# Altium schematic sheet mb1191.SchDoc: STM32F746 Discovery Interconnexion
size A4; Date: 25-FEB-2015; Author: A.B; CompanyName: STMicroelectronics; Address1: 12, Rue Jules HOROWITZ; Address2: 38019 Grenoble; Address3: FRANCE; DocumentNumber: MB1191; Revision: B-02; SheetNumber: 1; SheetTotal: 13; Project: STM32F746G-DISCO
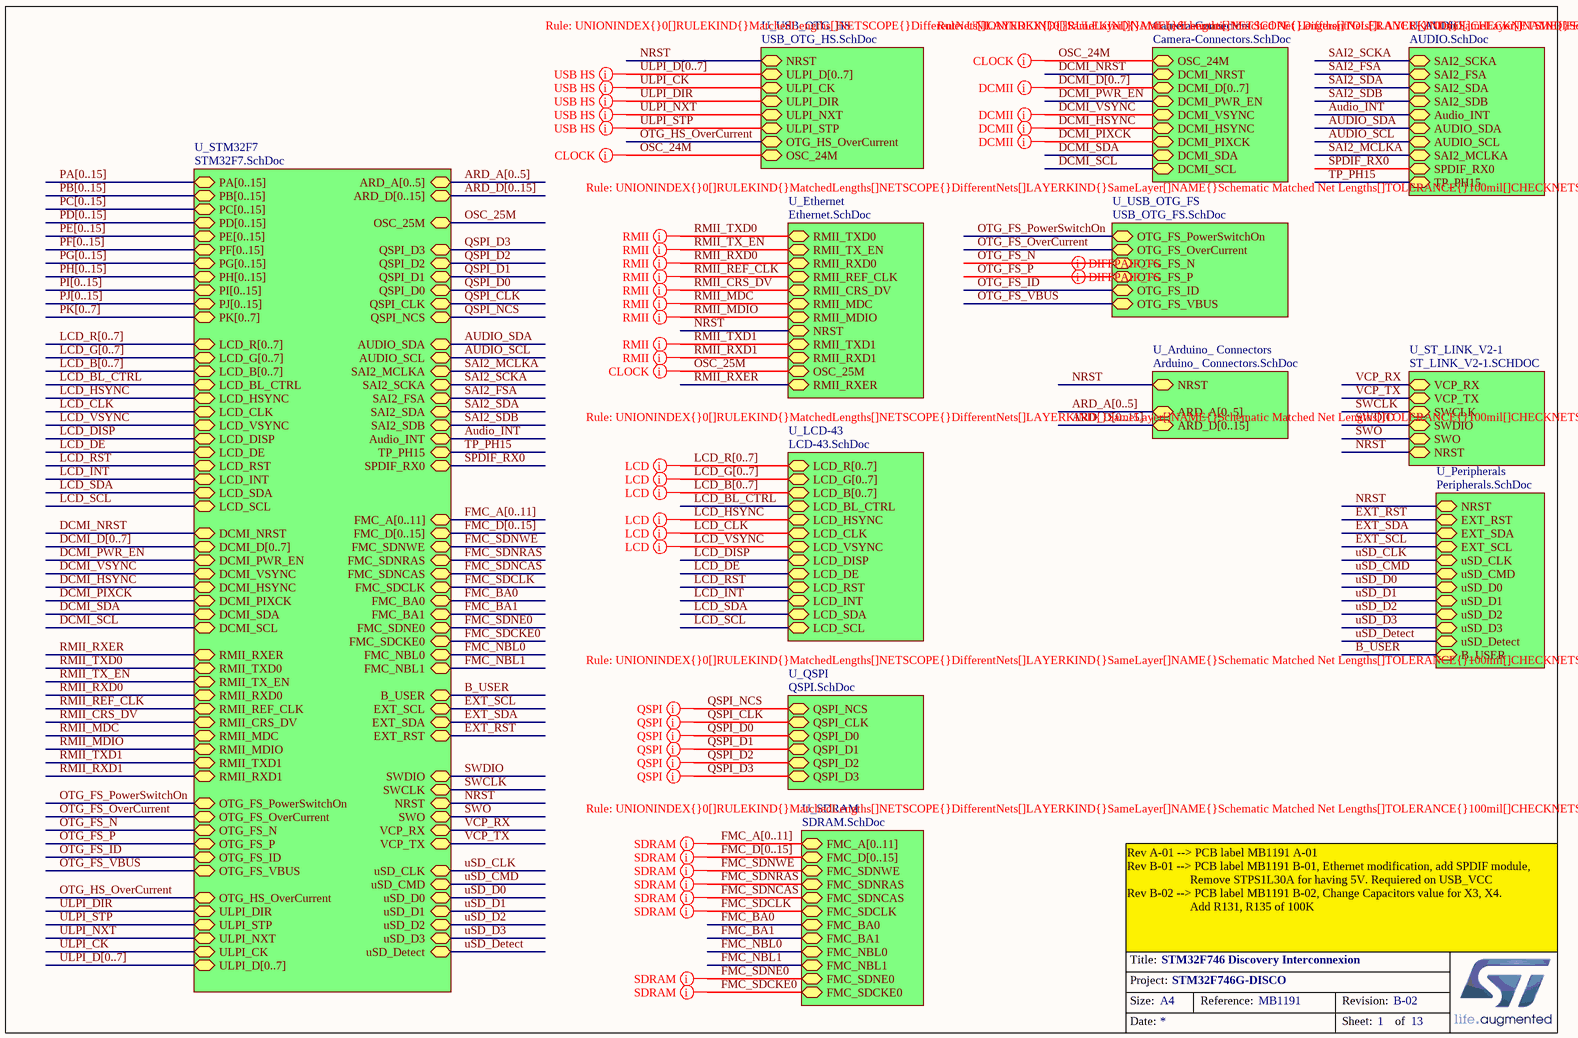
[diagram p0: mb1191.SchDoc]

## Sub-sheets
Camera-Connectors = Camera-Connectors.SchDoc: OSC_24M, DCMI_NRST, DCMI_D[0..7], DCMI_PWR_EN, DCMI_VSYNC, DCMI_HSYNC, DCMI_PIXCK, DCMI_SDA, DCMI_SCL
U_Arduino_ Connectors = Arduino_ Connectors.SchDoc: NRST, ARD_A[0..5], ARD_D[0..15]
U_AUDIO = AUDIO.SchDoc: AUDIO_SDA, AUDIO_SCL, SAI2_MCLKA, SPDIF_RX0, TP_PH15, SAI2_SCKA, SAI2_FSA, SAI2_SDA, SAI2_SDB, Audio_INT
U_Ethernet = Ethernet.SchDoc: RMII_TXD0, RMII_TX_EN, RMII_RXD0, RMII_REF_CLK, RMII_CRS_DV, RMII_MDC, RMII_MDIO, NRST, RMII_TXD1, RMII_RXD1, OSC_25M, RMII_RXER
U_LCD-43 = LCD-43.SchDoc: LCD_R[0..7], LCD_BL_CTRL, LCD_B[0..7], LCD_G[0..7], LCD_HSYNC, LCD_CLK, LCD_VSYNC, LCD_DISP, LCD_DE, LCD_RST, LCD_INT, LCD_SDA, LCD_SCL
U_Peripherals = Peripherals.SchDoc: NRST, EXT_RST, EXT_SCL, EXT_SDA, uSD_CLK, uSD_CMD, uSD_D0, uSD_D1, uSD_D2, uSD_D3, uSD_Detect, B_USER
U_QSPI = QSPI.SchDoc: QSPI_D0, QSPI_D3, QSPI_D1, QSPI_CLK, QSPI_NCS, QSPI_D2
U_SDRAM = SDRAM.SchDoc: FMC_A[0..11], FMC_D[0..15], FMC_SDNWE, FMC_SDNRAS, FMC_SDNCAS, FMC_SDCLK, FMC_BA0, FMC_BA1, FMC_NBL0, FMC_NBL1, FMC_SDNE0, FMC_SDCKE0
U_ST_LINK_V2-1 = ST_LINK_V2-1.SCHDOC: SWDIO, SWCLK, NRST, VCP_RX, VCP_TX, SWO
U_STM32F7 = STM32F7.SchDoc: PA[0..15], PB[0..15], PC[0..15], PD[0..15], PE[0..15], PF[0..15], PG[0..15], PH[0..15], PI[0..15], PJ[0..15], PK[0..7], OSC_25M, LCD_R[0..7], LCD_BL_CTRL, LCD_B[0..7], LCD_G[0..7], LCD_HSYNC, LCD_CLK, LCD_VSYNC, LCD_DISP, LCD_DE, LCD_RST, LCD_INT, LCD_SDA, LCD_SCL, DCMI_NRST, DCMI_D[0..7], DCMI_PWR_EN, DCMI_VSYNC, DCMI_HSYNC, DCMI_PIXCK, DCMI_SDA, DCMI_SCL, RMII_TXD0, RMII_TX_EN, RMII_RXD0, RMII_REF_CLK, RMII_CRS_DV, RMII_MDC, RMII_MDIO, RMII_TXD1, RMII_RXD1, ULPI_D[0..7], ULPI_CK, ULPI_DIR, ULPI_NXT, ULPI_STP, OTG_FS_N, OTG_FS_P, OTG_FS_ID, OTG_FS_VBUS, OTG_FS_PowerSwitchOn, OTG_FS_OverCurrent, QSPI_D0, QSPI_D3, QSPI_D1, QSPI_CLK, QSPI_NCS, AUDIO_SDA, AUDIO_SCL, SAI2_MCLKA, EXT_SCL, EXT_SDA, EXT_RST, uSD_CLK, uSD_CMD, uSD_D0, uSD_D1, uSD_D2, uSD_D3, uSD_Detect, SWDIO, SWCLK, NRST, SWO, VCP_RX, VCP_TX, FMC_A[0..11], FMC_D[0..15], FMC_SDNWE, FMC_SDNRAS, FMC_SDNCAS, FMC_SDCLK, FMC_BA0, FMC_BA1, FMC_SDNE0, FMC_SDCKE0, FMC_NBL0, FMC_NBL1, SPDIF_RX0, QSPI_D2, B_USER, ARD_A[0..5], ARD_D[0..15], RMII_RXER, OTG_HS_OverCurrent, SAI2_SCKA, SAI2_FSA, SAI2_SDA, SAI2_SDB, Audio_INT, TP_PH15
U_USB_OTG_FS = USB_OTG_FS.SchDoc: OTG_FS_PowerSwitchOn, OTG_FS_OverCurrent, OTG_FS_N, OTG_FS_P, OTG_FS_ID, OTG_FS_VBUS
U_USB_OTG_HS = USB_OTG_HS.SchDoc: ULPI_D[0..7], ULPI_CK, ULPI_DIR, ULPI_NXT, ULPI_STP, OSC_24M, NRST, OTG_HS_OverCurrent

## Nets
Audio_INT: sheet U_AUDIO/Audio_INT, sheet U_STM32F7/Audio_INT
AUDIO_SCL: sheet U_AUDIO/AUDIO_SCL, sheet U_STM32F7/AUDIO_SCL
AUDIO_SDA: sheet U_AUDIO/AUDIO_SDA, sheet U_STM32F7/AUDIO_SDA
B_USER: sheet U_Peripherals/B_USER, sheet U_STM32F7/B_USER
DCMI_HSYNC: sheet U_STM32F7/DCMI_HSYNC, sheet Camera-Connectors/DCMI_HSYNC
DCMI_NRST: sheet U_STM32F7/DCMI_NRST, sheet Camera-Connectors/DCMI_NRST
DCMI_PIXCK: sheet U_STM32F7/DCMI_PIXCK, sheet Camera-Connectors/DCMI_PIXCK
DCMI_PWR_EN: sheet U_STM32F7/DCMI_PWR_EN, sheet Camera-Connectors/DCMI_PWR_EN
DCMI_SCL: sheet U_STM32F7/DCMI_SCL, sheet Camera-Connectors/DCMI_SCL
DCMI_SDA: sheet U_STM32F7/DCMI_SDA, sheet Camera-Connectors/DCMI_SDA
DCMI_VSYNC: sheet U_STM32F7/DCMI_VSYNC, sheet Camera-Connectors/DCMI_VSYNC
EXT_RST: sheet U_Peripherals/EXT_RST, sheet U_STM32F7/EXT_RST
EXT_SCL: sheet U_Peripherals/EXT_SCL, sheet U_STM32F7/EXT_SCL
EXT_SDA: sheet U_Peripherals/EXT_SDA, sheet U_STM32F7/EXT_SDA
FMC_BA0: sheet U_SDRAM/FMC_BA0, sheet U_STM32F7/FMC_BA0
FMC_BA1: sheet U_SDRAM/FMC_BA1, sheet U_STM32F7/FMC_BA1
FMC_NBL0: sheet U_SDRAM/FMC_NBL0, sheet U_STM32F7/FMC_NBL0
FMC_NBL1: sheet U_SDRAM/FMC_NBL1, sheet U_STM32F7/FMC_NBL1
FMC_SDCKE0: sheet U_SDRAM/FMC_SDCKE0, sheet U_STM32F7/FMC_SDCKE0
FMC_SDCLK: sheet U_SDRAM/FMC_SDCLK, sheet U_STM32F7/FMC_SDCLK
FMC_SDNCAS: sheet U_SDRAM/FMC_SDNCAS, sheet U_STM32F7/FMC_SDNCAS
FMC_SDNE0: sheet U_SDRAM/FMC_SDNE0, sheet U_STM32F7/FMC_SDNE0
FMC_SDNRAS: sheet U_SDRAM/FMC_SDNRAS, sheet U_STM32F7/FMC_SDNRAS
FMC_SDNWE: sheet U_SDRAM/FMC_SDNWE, sheet U_STM32F7/FMC_SDNWE
LCD_BL_CTRL: sheet U_LCD-43/LCD_BL_CTRL, sheet U_STM32F7/LCD_BL_CTRL
LCD_CLK: sheet U_LCD-43/LCD_CLK, sheet U_STM32F7/LCD_CLK
LCD_DE: sheet U_LCD-43/LCD_DE, sheet U_STM32F7/LCD_DE
LCD_DISP: sheet U_LCD-43/LCD_DISP, sheet U_STM32F7/LCD_DISP
LCD_HSYNC: sheet U_LCD-43/LCD_HSYNC, sheet U_STM32F7/LCD_HSYNC
LCD_INT: sheet U_LCD-43/LCD_INT, sheet U_STM32F7/LCD_INT
LCD_RST: sheet U_LCD-43/LCD_RST, sheet U_STM32F7/LCD_RST
LCD_SCL: sheet U_LCD-43/LCD_SCL, sheet U_STM32F7/LCD_SCL
LCD_SDA: sheet U_LCD-43/LCD_SDA, sheet U_STM32F7/LCD_SDA
LCD_VSYNC: sheet U_LCD-43/LCD_VSYNC, sheet U_STM32F7/LCD_VSYNC
NRST: sheet U_ST_LINK_V2-1/NRST, sheet U_Peripherals/NRST, sheet U_Arduino_ Connectors/NRST, sheet U_USB_OTG_HS/NRST, sheet U_STM32F7/NRST, sheet U_Ethernet/NRST
OSC_24M: sheet U_USB_OTG_HS/OSC_24M, sheet Camera-Connectors/OSC_24M
OSC_25M: sheet U_STM32F7/OSC_25M, sheet U_Ethernet/OSC_25M
OTG_FS_ID: sheet U_USB_OTG_FS/OTG_FS_ID, sheet U_STM32F7/OTG_FS_ID
OTG_FS_N: sheet U_USB_OTG_FS/OTG_FS_N, sheet U_STM32F7/OTG_FS_N
OTG_FS_OverCurrent: sheet U_USB_OTG_FS/OTG_FS_OverCurrent, sheet U_STM32F7/OTG_FS_OverCurrent
OTG_FS_P: sheet U_USB_OTG_FS/OTG_FS_P, sheet U_STM32F7/OTG_FS_P
OTG_FS_PowerSwitchOn: sheet U_USB_OTG_FS/OTG_FS_PowerSwitchOn, sheet U_STM32F7/OTG_FS_PowerSwitchOn
OTG_FS_VBUS: sheet U_USB_OTG_FS/OTG_FS_VBUS, sheet U_STM32F7/OTG_FS_VBUS
OTG_HS_OverCurrent: sheet U_USB_OTG_HS/OTG_HS_OverCurrent, sheet U_STM32F7/OTG_HS_OverCurrent
QSPI_CLK: sheet U_QSPI/QSPI_CLK, sheet U_STM32F7/QSPI_CLK
QSPI_D0: sheet U_QSPI/QSPI_D0, sheet U_STM32F7/QSPI_D0
QSPI_D1: sheet U_QSPI/QSPI_D1, sheet U_STM32F7/QSPI_D1
QSPI_D2: sheet U_QSPI/QSPI_D2, sheet U_STM32F7/QSPI_D2
QSPI_D3: sheet U_QSPI/QSPI_D3, sheet U_STM32F7/QSPI_D3
QSPI_NCS: sheet U_QSPI/QSPI_NCS, sheet U_STM32F7/QSPI_NCS
RMII_CRS_DV: sheet U_STM32F7/RMII_CRS_DV, sheet U_Ethernet/RMII_CRS_DV
RMII_MDC: sheet U_STM32F7/RMII_MDC, sheet U_Ethernet/RMII_MDC
RMII_MDIO: sheet U_STM32F7/RMII_MDIO, sheet U_Ethernet/RMII_MDIO
RMII_REF_CLK: sheet U_STM32F7/RMII_REF_CLK, sheet U_Ethernet/RMII_REF_CLK
RMII_RXD0: sheet U_STM32F7/RMII_RXD0, sheet U_Ethernet/RMII_RXD0
RMII_RXD1: sheet U_STM32F7/RMII_RXD1, sheet U_Ethernet/RMII_RXD1
RMII_RXER: sheet U_STM32F7/RMII_RXER, sheet U_Ethernet/RMII_RXER
RMII_TX_EN: sheet U_STM32F7/RMII_TX_EN, sheet U_Ethernet/RMII_TX_EN
RMII_TXD0: sheet U_STM32F7/RMII_TXD0, sheet U_Ethernet/RMII_TXD0
RMII_TXD1: sheet U_STM32F7/RMII_TXD1, sheet U_Ethernet/RMII_TXD1
SAI2_FSA: sheet U_AUDIO/SAI2_FSA, sheet U_STM32F7/SAI2_FSA
SAI2_MCLKA: sheet U_AUDIO/SAI2_MCLKA, sheet U_STM32F7/SAI2_MCLKA
SAI2_SCKA: sheet U_AUDIO/SAI2_SCKA, sheet U_STM32F7/SAI2_SCKA
SAI2_SDA: sheet U_AUDIO/SAI2_SDA, sheet U_STM32F7/SAI2_SDA
SAI2_SDB: sheet U_AUDIO/SAI2_SDB, sheet U_STM32F7/SAI2_SDB
SPDIF_RX0: sheet U_AUDIO/SPDIF_RX0, sheet U_STM32F7/SPDIF_RX0
SWCLK: sheet U_ST_LINK_V2-1/SWCLK, sheet U_STM32F7/SWCLK
SWDIO: sheet U_ST_LINK_V2-1/SWDIO, sheet U_STM32F7/SWDIO
SWO: sheet U_ST_LINK_V2-1/SWO, sheet U_STM32F7/SWO
TP_PH15: sheet U_AUDIO/TP_PH15, sheet U_STM32F7/TP_PH15
ULPI_CK: sheet U_USB_OTG_HS/ULPI_CK, sheet U_STM32F7/ULPI_CK
ULPI_DIR: sheet U_USB_OTG_HS/ULPI_DIR, sheet U_STM32F7/ULPI_DIR
ULPI_NXT: sheet U_USB_OTG_HS/ULPI_NXT, sheet U_STM32F7/ULPI_NXT
ULPI_STP: sheet U_USB_OTG_HS/ULPI_STP, sheet U_STM32F7/ULPI_STP
uSD_CLK: sheet U_Peripherals/uSD_CLK, sheet U_STM32F7/uSD_CLK
uSD_CMD: sheet U_Peripherals/uSD_CMD, sheet U_STM32F7/uSD_CMD
uSD_D0: sheet U_Peripherals/uSD_D0, sheet U_STM32F7/uSD_D0
uSD_D1: sheet U_Peripherals/uSD_D1, sheet U_STM32F7/uSD_D1
uSD_D2: sheet U_Peripherals/uSD_D2, sheet U_STM32F7/uSD_D2
uSD_D3: sheet U_Peripherals/uSD_D3, sheet U_STM32F7/uSD_D3
uSD_Detect: sheet U_Peripherals/uSD_Detect, sheet U_STM32F7/uSD_Detect
VCP_RX: sheet U_ST_LINK_V2-1/VCP_RX, sheet U_STM32F7/VCP_RX
VCP_TX: sheet U_ST_LINK_V2-1/VCP_TX, sheet U_STM32F7/VCP_TX

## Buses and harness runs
bus ARD_A[0..5] = sheet U_Arduino_ Connectors/ARD_A[0..5]
bus ARD_A[0..5] = sheet U_STM32F7/ARD_A[0..5]
bus ARD_D[0..15] = sheet U_Arduino_ Connectors/ARD_D[0..15]
bus ARD_D[0..15] = sheet U_STM32F7/ARD_D[0..15]
bus DCMI_D[0..7] = sheet Camera-Connectors/DCMI_D[0..7]
bus DCMI_D[0..7] = sheet U_STM32F7/DCMI_D[0..7]
bus FMC_A[0..11] = sheet U_SDRAM/FMC_A[0..11]
bus FMC_A[0..11] = sheet U_STM32F7/FMC_A[0..11]
bus FMC_D[0..15] = sheet U_SDRAM/FMC_D[0..15]
bus FMC_D[0..15] = sheet U_STM32F7/FMC_D[0..15]
bus LCD_B[0..7] = sheet U_LCD-43/LCD_B[0..7]
bus LCD_B[0..7] = sheet U_STM32F7/LCD_B[0..7]
bus LCD_G[0..7] = sheet U_LCD-43/LCD_G[0..7]
bus LCD_G[0..7] = sheet U_STM32F7/LCD_G[0..7]
bus LCD_R[0..7] = sheet U_LCD-43/LCD_R[0..7]
bus LCD_R[0..7] = sheet U_STM32F7/LCD_R[0..7]
bus PA[0..15] = sheet U_STM32F7/PA[0..15]
bus PB[0..15] = sheet U_STM32F7/PB[0..15]
bus PC[0..15] = sheet U_STM32F7/PC[0..15]
bus PD[0..15] = sheet U_STM32F7/PD[0..15]
bus PE[0..15] = sheet U_STM32F7/PE[0..15]
bus PF[0..15] = sheet U_STM32F7/PF[0..15]
bus PG[0..15] = sheet U_STM32F7/PG[0..15]
bus PH[0..15] = sheet U_STM32F7/PH[0..15]
bus PI[0..15] = sheet U_STM32F7/PI[0..15]
bus PJ[0..15] = sheet U_STM32F7/PJ[0..15]
bus PK[0..7] = sheet U_STM32F7/PK[0..7]
bus ULPI_D[0..7] = sheet U_STM32F7/ULPI_D[0..7]
bus ULPI_D[0..7] = sheet U_USB_OTG_HS/ULPI_D[0..7]

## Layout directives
rule Matched Net Lengths [Tolerance = 100mil]: (no net found under the mark), DCMI_HSYNC, DCMI_PIXCK, DCMI_VSYNC, FMC_SDCKE0, FMC_SDCLK, FMC_SDNCAS, FMC_SDNE0, FMC_SDNRAS, FMC_SDNWE, LCD_CLK, LCD_HSYNC, LCD_VSYNC, QSPI_CLK, QSPI_D0, QSPI_D1, QSPI_D2, QSPI_D3, QSPI_NCS, RMII_CRS_DV, RMII_MDC, RMII_MDIO, RMII_REF_CLK, RMII_RXD0, RMII_RXD1, RMII_TX_EN, RMII_TXD0, RMII_TXD1, ULPI_CK, ULPI_DIR, ULPI_NXT, ULPI_STP
rule Undefined: OSC_24M, OSC_25M
differential pair: OTG_FS_N, OTG_FS_P

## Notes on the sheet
- Rev A-01 --> PCB label MB1191 A-01
  Rev B-01 --> PCB label MB1191 B-01, Ethernet modification, add SPDIF module,
  Remove STPS1L30A for having 5V. Requiered on USB_VCC
  Rev B-02 --> PCB label MB1191 B-02, Change Capacitors value for X3, X4.
  Add R131, R135 of 100K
